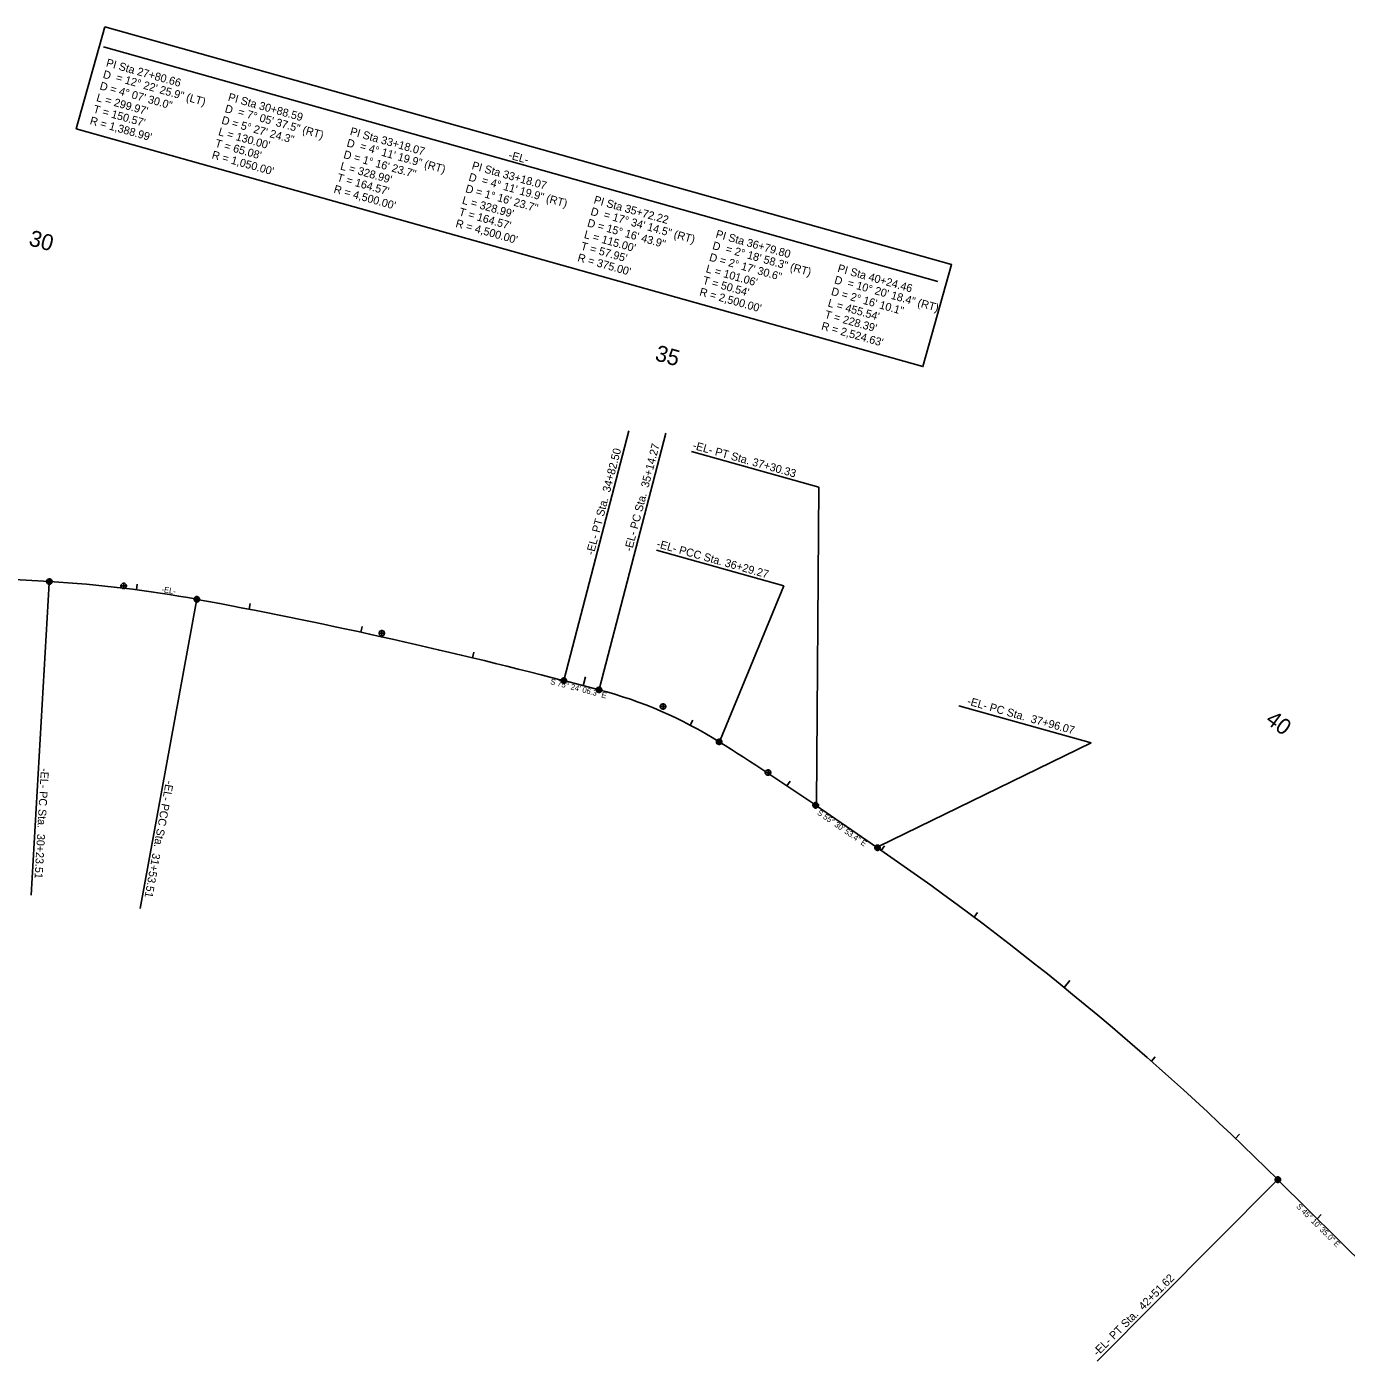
# Model space of a CAD drawing. Extents: x 928071 to 937324, y 684061 to 686812.
# Drawn here: x 929834 to 930989, y 685072 to 686240 of the extents above; entities that cross this region are included whole.
import ezdxf

# ---------------------------------------------------------------- set-up
doc = ezdxf.new("R2010")
doc.units = 0
for name, color, linetype in [('COGO Default Chain', 7, 'Continuous'), ('COGO Default Curve', 7, 'Continuous'), ('Cogo Default Point CELL', 7, 'Continuous'), ('Default', 7, 'Continuous'), ('Exist Horizontal Alignment', 7, 'Continuous'), ('Exist Horizontal Alignment Curve and Spiral Data', 7, 'Continuous'), ('Exist Horizontal Alignment Direction Label', 7, 'Continuous'), ('Exist Horizontal Alignment Station Label', 7, 'Continuous'), ('Exist Horizontal Alignment Tick Label', 7, 'Continuous'), ('Exist Horizontal Alignment Tick Large', 7, 'Continuous'), ('Exist Horizontal Alignment Tick Small', 7, 'Continuous'), ('Prop DSN Text', 7, 'Continuous')]:
    doc.layers.add(name, color=color, linetype=linetype)

msp = doc.modelspace()

# ---------------------------------------------------------------- linework, layer by layer
at = {"layer": 'COGO Default Chain'}
for p, q in [((929761, 685759.6), (929854.3, 685754.2)), ((930304.4, 685667.5), (930335.2, 685659.5)), ((930524.7, 685558.5), (930578.9, 685521.3)), ((930929.2, 685230.9), (931008.1, 685152.5))]:
    msp.add_line(p, q, dxfattribs=at)
for centre, radius, start, end in [((929793.6, 684706), 1050, 79.5906, 86.6844), ((929170.2, 681312.7), 4500, 75.4017, 79.5906), ((930240.6, 685296.6), 375, 57.831, 75.4017), ((929109.3, 683497.8), 2500, 55.5148, 57.831), ((929149.5, 683440.3), 2524.6, 45.1764, 55.5148)]:
    msp.add_arc(centre, radius, start, end, dxfattribs=at)
at = {"layer": 'COGO Default Curve'}
for centre, radius, start, end in [((929793.6, 684706), 1050, 79.5906, 86.6844), ((929170.2, 681312.7), 4500, 75.4017, 79.5906), ((930240.6, 685296.6), 375, 57.831, 75.4017), ((929109.3, 683497.8), 2500, 55.5148, 57.831), ((929149.5, 683440.3), 2524.6, 45.1764, 55.5148)]:
    msp.add_arc(centre, radius, start, end, dxfattribs=at)
at = {"layer": 'Cogo Default Point CELL'}
for points in [[(929851.3, 685754.2), (929854.3, 685754.2)], [(929854.3, 685757.2), (929854.3, 685754.2)], [(929854.3, 685754.2), (929857.3, 685754.2)], [(929854.3, 685754.2), (929854.3, 685751.2)], [(929916.3, 685750.4), (929919.3, 685750.4)], [(929919.3, 685753.4), (929919.3, 685750.4)], [(929919.3, 685750.4), (929922.3, 685750.4)], [(929919.3, 685750.4), (929919.3, 685747.4)], [(929980.3, 685738.7), (929983.3, 685738.7)], [(929980.3, 685738.7), (929983.3, 685738.7)], [(929983.3, 685741.7), (929983.3, 685738.7)], [(929983.3, 685741.7), (929983.3, 685738.7)], [(929983.3, 685738.7), (929986.3, 685738.7)], [(929983.3, 685738.7), (929983.3, 685735.7)], [(929983.3, 685738.7), (929986.3, 685738.7)], [(929983.3, 685738.7), (929983.3, 685735.7)], [(930142.2, 685709), (930145.2, 685709)], [(930145.2, 685712), (930145.2, 685709)], [(930145.2, 685709), (930148.2, 685709)], [(930145.2, 685709), (930145.2, 685706)], [(930301.4, 685667.5), (930304.4, 685667.5)], [(930304.4, 685670.5), (930304.4, 685667.5)], [(930304.4, 685667.5), (930307.4, 685667.5)], [(930304.4, 685667.5), (930304.4, 685664.5)], [(930332.2, 685659.5), (930335.2, 685659.5)], [(930335.2, 685662.5), (930335.2, 685659.5)], [(930335.2, 685659.5), (930338.2, 685659.5)], [(930335.2, 685659.5), (930335.2, 685656.5)], [(930388.2, 685644.9), (930391.2, 685644.9)], [(930391.2, 685647.9), (930391.2, 685644.9)], [(930391.2, 685644.9), (930394.2, 685644.9)], [(930391.2, 685644.9), (930391.2, 685641.9)], [(930437.3, 685614), (930440.3, 685614)], [(930437.3, 685614), (930440.3, 685614)], [(930440.3, 685617), (930440.3, 685614)], [(930440.3, 685617), (930440.3, 685614)], [(930440.3, 685614), (930443.3, 685614)], [(930440.3, 685614), (930440.3, 685611)], [(930440.3, 685614), (930443.3, 685614)], [(930440.3, 685614), (930440.3, 685611)], [(930480.1, 685587.1), (930483.1, 685587.1)], [(930483.1, 685590.1), (930483.1, 685587.1)], [(930483.1, 685587.1), (930486.1, 685587.1)], [(930483.1, 685587.1), (930483.1, 685584.1)], [(930524.7, 685561.5), (930524.7, 685558.5)], [(930521.7, 685558.5), (930524.7, 685558.5)], [(930524.7, 685558.5), (930527.7, 685558.5)], [(930524.7, 685558.5), (930524.7, 685555.5)], [(930575.9, 685521.3), (930578.9, 685521.3)], [(930578.9, 685524.3), (930578.9, 685521.3)], [(930578.9, 685521.3), (930581.9, 685521.3)], [(930578.9, 685521.3), (930578.9, 685518.3)], [(930926.2, 685230.9), (930929.2, 685230.9)], [(930929.2, 685233.9), (930929.2, 685230.9)], [(930929.2, 685230.9), (930932.2, 685230.9)], [(930929.2, 685230.9), (930929.2, 685227.9)]]:
    msp.add_lwpolyline(points, dxfattribs=at)
for centre in [(929854.3, 685754.2), (929919.3, 685750.4), (929983.3, 685738.7), (929983.3, 685738.7), (930145.2, 685709), (930304.4, 685667.5), (930335.2, 685659.5), (930391.2, 685644.9), (930440.3, 685614), (930440.3, 685614), (930483.1, 685587.1), (930524.7, 685558.5), (930578.9, 685521.3), (930929.2, 685230.9)]:
    msp.add_circle(centre, 2.34, dxfattribs=at)
at = {"layer": 'Default'}
for p, q in [((929854.3, 685754.2), (929761, 685759.6)), ((930335.2, 685659.5), (930304.4, 685667.5)), ((930578.9, 685521.3), (930524.7, 685558.5)), ((931008.1, 685152.5), (930929.2, 685230.9))]:
    msp.add_line(p, q, dxfattribs=at)
msp.add_lwpolyline([(929902.9, 686239.6), (930643.7, 686031.5), (930618.6, 685942.3), (929877.8, 686150.4)], close=True, dxfattribs=at)
for centre, radius, start, end in [((929793.6, 684706), 1050, 79.5906, 86.6844), ((929170.2, 681312.7), 4500, 75.4017, 79.5906), ((930240.6, 685296.6), 375, 57.831, 75.4017), ((929109.3, 683497.8), 2500, 55.5148, 57.831), ((929149.5, 683440.3), 2524.6, 45.1764, 55.5148)]:
    msp.add_arc(centre, radius, start, end, dxfattribs=at)
at = {"layer": 'Exist Horizontal Alignment'}
for p, q in [((929761, 685759.6), (929854.3, 685754.2)), ((930304.4, 685667.5), (930335.2, 685659.5)), ((930524.7, 685558.5), (930578.9, 685521.3)), ((930929.2, 685230.9), (931008.1, 685152.5))]:
    msp.add_line(p, q, dxfattribs=at)
for centre, radius, start, end in [((929793.6, 684706), 1050, 79.5906, 86.6844), ((929170.2, 681312.7), 4500, 75.4017, 79.5906), ((930240.6, 685296.6), 375, 57.831, 75.4017), ((929109.3, 683497.8), 2500, 55.5148, 57.831), ((929149.5, 683440.3), 2524.6, 45.1764, 55.5148)]:
    msp.add_arc(centre, radius, start, end, dxfattribs=at)
at = {"layer": 'Exist Horizontal Alignment Curve and Spiral Data'}
msp.add_line((929901.5, 686221.9), (930631.7, 686016.8), dxfattribs=at)
at = {"layer": 'Exist Horizontal Alignment Station Label'}
for p, q in [((930361.4, 685886.2), (930304.8, 685668.9)), ((930393.6, 685883.9), (930335.5, 685660.9)), ((930416.2, 685868.1), (930527.6, 685836.8)), ((930525.6, 685559.7), (930527.6, 685836.8)), ((930385.4, 685781.8), (930496.8, 685750.5)), ((929854.2, 685752.7), (929838.4, 685479.7)), ((930441.1, 685615.3), (930496.8, 685750.5)), ((929983, 685737.2), (929933.6, 685468.2)), ((930765.7, 685613), (930649.9, 685645.6)), ((930579.8, 685522.5), (930765.7, 685613)), ((930928.1, 685229.9), (930771.2, 685072))]:
    msp.add_line(p, q, dxfattribs=at)
for centre in [(929854.3, 685754.2), (929983.3, 685738.7), (930304.4, 685667.5), (930335.2, 685659.5), (930440.3, 685614), (930524.7, 685558.5), (930578.9, 685521.3), (930929.2, 685230.9)]:
    msp.add_circle(centre, 1.5, dxfattribs=at)
at = {"layer": 'Exist Horizontal Alignment Tick Large'}
for p, q in [((930321.4, 685663.1), (930323.4, 685670.8)), ((930742.2, 685399.1), (930747.2, 685405.3))]:
    msp.add_line(p, q, dxfattribs=at)
at = {"layer": 'Exist Horizontal Alignment Tick Small'}
for p, q in [((929930.5, 685747), (929931.1, 685752)), ((930029, 685730), (930029.9, 685735)), ((930126.9, 685709.9), (930128, 685714.8)), ((930224.4, 685687.5), (930225.6, 685692.4)), ((930414.9, 685628.6), (930417.3, 685633)), ((930499.6, 685575.5), (930502.4, 685579.7)), ((930582.2, 685519), (930585, 685523.1)), ((930663.4, 685460.7), (930666.4, 685464.7)), ((930818.5, 685334.5), (930821.8, 685338.3)), ((930892.2, 685267), (930895.7, 685270.6)), ((930963.5, 685196.8), (930967, 685200.4))]:
    msp.add_line(p, q, dxfattribs=at)

# ---------------------------------------------------------------- texts
at = {"layer": 'Exist Horizontal Alignment Curve and Spiral Data'}
for s, p in [('PI Sta 27+80.66', (929903.4, 686205.1)), ('D', (929900.6, 686195)), ('= 12%%d 22\' 25.9" (LT)', (929912, 686192.2)), ("L = 299.97'", (929894.9, 686174.7)), ('D = 4%%d 07\' 30.0"', (929897.8, 686184.9)), ('PI Sta 30+88.59', (930010.1, 686175.1)), ("T = 150.57'", (929892.1, 686164.6)), ('D', (930007.3, 686165)), ("R = 1,388.99'", (929889.2, 686154.5)), ('D = 5%%d 27\' 24.3"', (930004.4, 686154.9)), ('= 7%%d 05\' 37.5" (RT)', (930018.7, 686162.2)), ("L = 130.00'", (930001.6, 686144.8)), ('PI Sta 33+18.07', (930116.8, 686145.1)), ("T = 65.08'", (929998.7, 686134.7)), ('D', (930113.9, 686135)), ('= 4%%d 11\' 19.9" (RT)', (930125.4, 686132.2)), ("R = 1,050.00'", (929995.9, 686124.6)), ('D = 1%%d 16\' 23.7"', (930111.1, 686124.9)), ('PI Sta 33+18.07', (930223.4, 686115.2)), ('-EL-', (930255.5, 686124.4)), ("T = 164.57'", (930105.4, 686104.7)), ("L = 328.99'", (930108.3, 686114.8)), ('D', (930220.6, 686105.1)), ("R = 4,500.00'", (930102.6, 686094.6)), ('D = 1%%d 16\' 23.7"', (930217.8, 686095)), ('= 4%%d 11\' 19.9" (RT)', (930232, 686102.3)), ("L = 328.99'", (930214.9, 686084.9)), ('PI Sta 35+72.22', (930330.1, 686085.2)), ("T = 164.57'", (930212.1, 686074.7)), ('D', (930327.3, 686075.1)), ('= 17%%d 34\' 14.5" (RT)', (930338.7, 686072.3)), ("R = 4,500.00'", (930209.2, 686064.6)), ('D = 15%%d 16\' 43.9"', (930324.4, 686065)), ("L = 115.00'", (930321.6, 686054.9)), ('D', (930433.9, 686045.2)), ('PI Sta 36+79.80', (930436.8, 686055.3)), ("R = 375.00'", (930315.9, 686034.7)), ("T = 57.95'", (930318.7, 686044.8)), ('D = 2%%d 17\' 30.6"', (930431.1, 686035)), ('= 2%%d 18\' 58.3" (RT)', (930445.4, 686042.3)), ("L = 101.06'", (930428.2, 686024.9)), ('PI Sta 40+24.46', (930543.4, 686025.3)), ("T = 50.54'", (930425.4, 686014.8)), ('D', (930540.6, 686015.2)), ('= 10%%d 20\' 18.4" (RT)', (930552, 686012.4)), ("R = 2,500.00'", (930422.6, 686004.7)), ('D = 2%%d 16\' 10.1"', (930537.8, 686005.1)), ("L = 455.54'", (930534.9, 685995)), ("T = 228.39'", (930532.1, 685984.9)), ("R = 2,524.63'", (930529.2, 685974.8))]:
    msp.add_text(s, height=7, rotation=344.3105, dxfattribs=at).set_placement(p)
at = {"layer": 'Exist Horizontal Alignment Direction Label'}
for s, rotation, p in [('S 75%%d 24\' 06.3" E', 345.4017, (930292.2, 685664.6)), ('S 55%%d 30\' 53.4" E', 325.5148, (930525.6, 685550.8)), ('S 45%%d 10\' 35.0" E', 315.1764, (930944.9, 685207))]:
    msp.add_text(s, height=5, rotation=rotation, dxfattribs=at).set_placement(p)
at = {"layer": 'Exist Horizontal Alignment Station Label'}
for s, rotation, p in [('-EL- PT Sta.  34+82.50', 75.4017, (930330.5, 685776.9)), ('-EL- PC Sta.  35+14.27', 75.4017, (930363.9, 685780)), ('-EL- PT Sta. 37+30.33', 344.3105, (930416.6, 685870.4)), ('-EL- PCC Sta. 36+29.27', 344.3105, (930385.1, 685784.3)), ('-EL- PC Sta.  37+96.07', 344.3105, (930656.8, 685646.7)), ('-EL- PC Sta.  30+23.51', 266.6844, (929846.9, 685591.2)), ('-EL- PCC Sta.  31+53.51', 259.5906, (929956.3, 685580.4)), ('-EL- PT Sta.  42+51.62', 45.1764, (930771.5, 685076.1))]:
    msp.add_text(s, height=7, rotation=rotation, dxfattribs=at).set_placement(p)
at = {"layer": 'Exist Horizontal Alignment Tick Label'}
for s, rotation, p in [('30', 344.3106, (929835.5, 686048.6)), ('35', 344.3106, (930383.4, 685948)), ('40', 323.1561, (930917.5, 685631.3))]:
    msp.add_text(s, height=14, rotation=rotation, dxfattribs=at).set_placement(p)
at = {"layer": 'Prop DSN Text'}
msp.add_text('-EL-', height=5, rotation=350.8379, dxfattribs=at).set_placement((929952.1, 685745.1))

doc.saveas('drawing.dxf')
